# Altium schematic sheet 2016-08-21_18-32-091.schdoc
size 387 x 177 mm; SheetNumber: 1; SheetTotal: 1
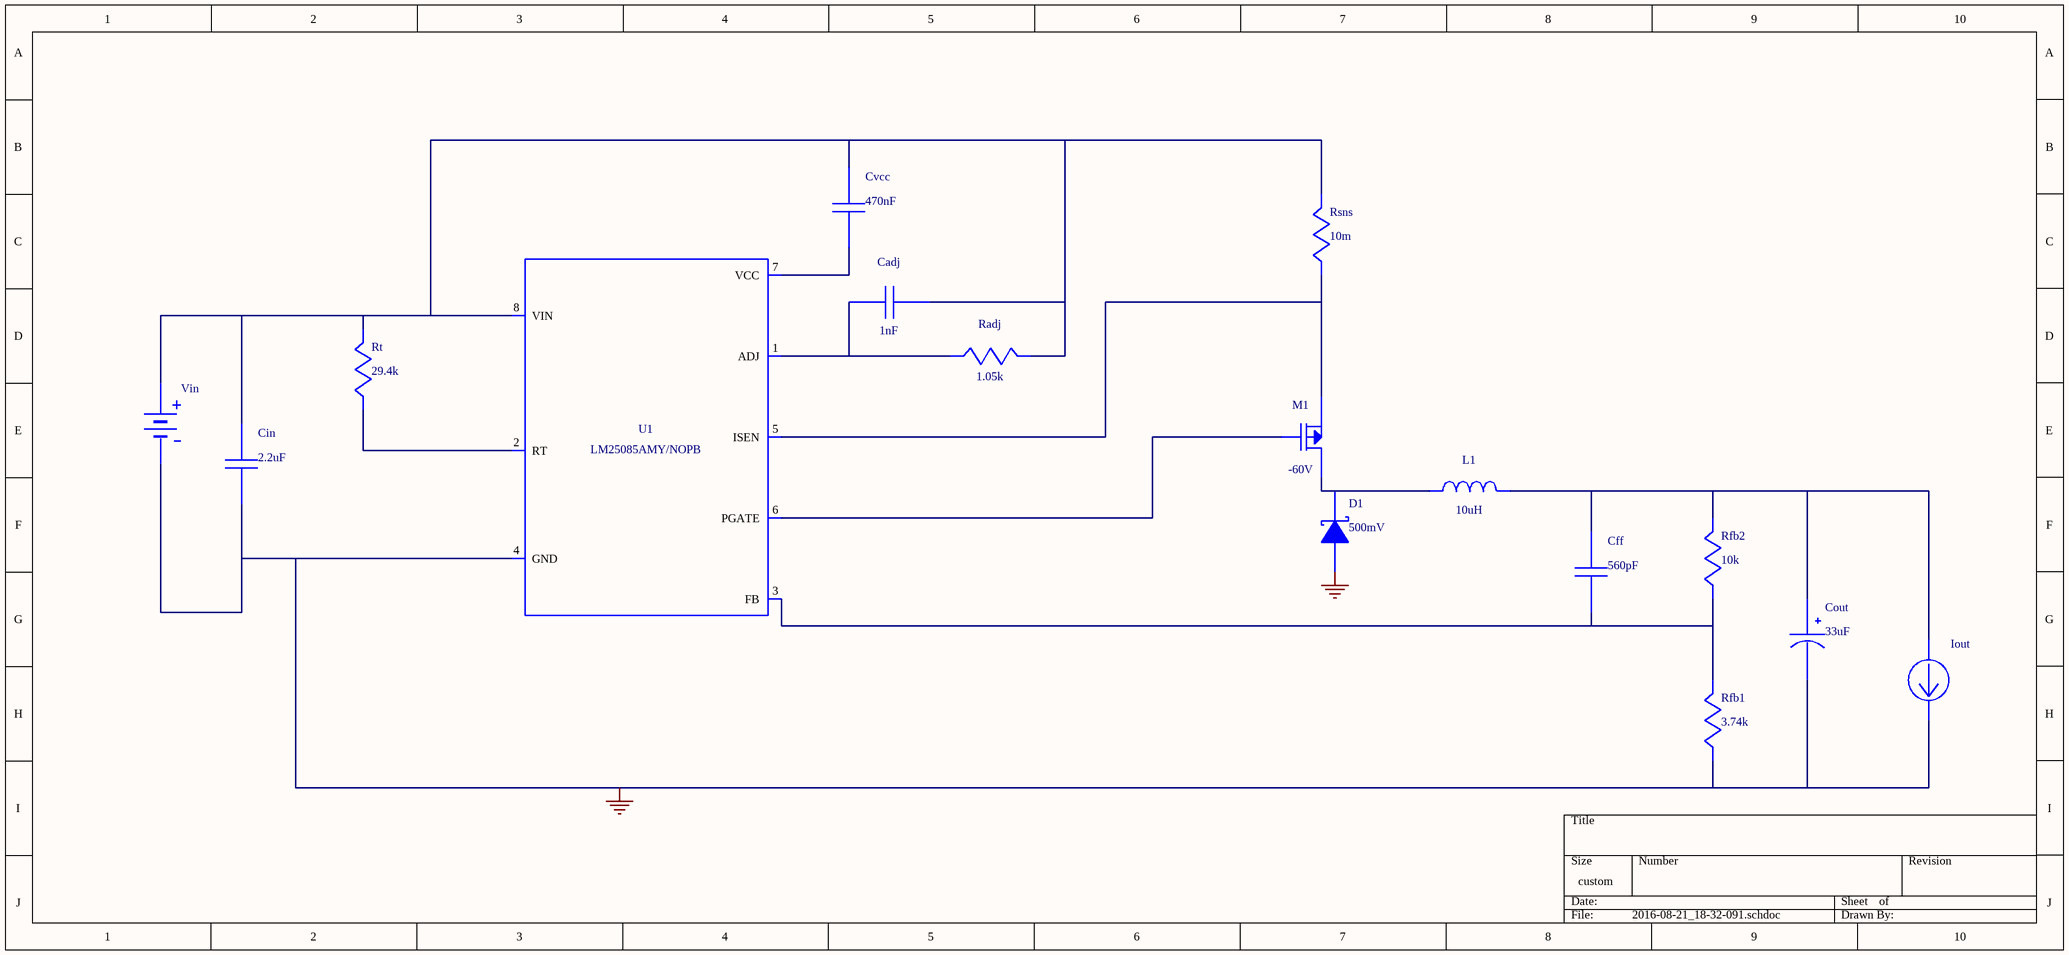
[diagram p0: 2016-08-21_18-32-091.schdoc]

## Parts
Cadj  value 1nF  (hidden comment: CL21C102JBCNFNC)
Cff  value 560pF  (hidden comment: C0805C561K5RACTU)
Cin  value 2.2uF  (hidden comment: GRM31CR71H225KA88L)
Cout  value 33uF  (hidden comment: TPSA336K006R0600)
Cvcc  value 470nF  (hidden comment: 0805YC474KAT2A)
D1  value 500mV  (hidden comment: B340A-13-F)
Iout  WB_CURRENT_LOAD  (value not drawn)
L1  value 10uH  (hidden comment: VLP8040T-100M)
M1  value -60V  (hidden comment: FDC5614P)
Radj  value 1.05k  (hidden comment: CRCW04021K05FKED)
Rfb1  value 3.74k  (hidden comment: CRCW04023K74FKED)
Rfb2  value 10k  (hidden comment: CRCW040210K0FKED)
Rsns  value 10m  (hidden comment: CSR1206FK10L0)
Rt  value 29.4k  (hidden comment: CRCW040229K4FKED)
U1  LM5085MY/NOPB  (value not drawn)
Vin  WB_BATTERY  (value not drawn)

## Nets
0: Cin.2 Cout.2(-) D1.2(A) Iout.2(-) Rfb1.2 U1.4(GND) U1.9(EP) Vin.2(-)
NetCadj_1: Cadj.1 Cin.1 Cvcc.1 Radj.1 Rsns.1 Rt.1 U1.8(VIN) Vin.1(+)
NetCadj_2: Cadj.2 Radj.2 U1.1(ADJ)
NetCff_1: Cff.1 Cout.1(+) Iout.1(+) L1.2 Rfb2.1
NetCff_2: Cff.2 Rfb1.1 Rfb2.2 U1.3(FB)
NetCvcc_2: Cvcc.2 U1.7(VCC)
NetD1_1: D1.1(K) L1.1 M1.1(Drain) M1.2(Drain) M1.5(Drain) M1.6(Drain)
NetM1_3: M1.3(Gate) U1.6(PGATE)
NetM1_4: M1.4(Source) Rsns.2 U1.5(ISEN)
NetRt_2: Rt.2 U1.2(RT)

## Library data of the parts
Cadj = CL21C102JBCNFNC: Manufacturer Name: Samsung Electro-Mechanics
Cff = C0805C561K5RACTU: Manufacturer Name: Kemet
Cin = GRM31CR71H225KA88L: GRM31CR71H225KA8; Manufacturer Name: MuRata
Cout = TPSA336K006R0600: Manufacturer Name: AVX
Cvcc = 0805YC474KAT2A: Manufacturer Name: AVX
D1 = B340A-13-F: Manufacturer Name: Diodes Inc.
L1 = VLP8040T-100M: Unknown; Manufacturer Name: TDK
M1 = FDC5614P: Manufacturer Name: Fairchild Semiconductor
Radj = CRCW04021K05FKED: Manufacturer Name: Vishay-Dale
Rfb1 = CRCW04023K74FKED: Manufacturer Name: Vishay-Dale
Rfb2 = CRCW040210K0FKED: Manufacturer Name: Vishay-Dale
Rsns = CSR1206FK10L0: Manufacturer Name: Stackpole Electronics Inc
Rt = CRCW040229K4FKED: Manufacturer Name: Vishay-Dale
U1 = LM5085MY/NOPB: LM25085AMY/NOPB; Manufacturer Name: Texas Instruments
